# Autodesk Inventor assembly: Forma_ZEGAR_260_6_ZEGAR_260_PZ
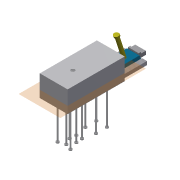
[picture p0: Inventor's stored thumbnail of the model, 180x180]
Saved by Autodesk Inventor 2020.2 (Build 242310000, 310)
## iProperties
Created: 2015-01
Part Number: Forma_ZEGAR_260_6_ZEGAR_260_PZ
Document SubType Name: Assembly
Designer: F.Stasiak
Catalog Web Link: www.expertbooks.pl
Manager: www.cadconsulting.pl
Company: Fabian Stasiak CAD Consulting
Author: F.Stasiak
Subject: Zbiór ćwiczeń. Autodesk Inventor 2020. Kurs Professional
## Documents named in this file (21)
- C:\2020_Kurs_Professional\R6 Formy\Komponenty\Forma_ZEGAR_260_6_ZEGAR_260_PZ.iam
- C:\2020_Kurs_Professional\R6 Formy\Komponenty\Forma_ZEGAR_260_6_ZEGAR_260_MP.ipt
- C:\2020_Kurs_Professional\R6 Formy\Komponenty\Forma_ZEGAR_260_6_ZEGAR_260_WP.ipt
- C:\2020_Kurs_Professional\R6 Formy\Komponenty\Forma_ZEGAR_260_6_ZEGAR_260_CR_Base.ipt
- C:\2020_Kurs_Professional\R6 Formy\Komponenty\Forma_ZEGAR_260_6_ZEGAR_260_CV_Base.ipt
- C:\2020_Kurs_Professional\R6 Formy\Komponenty\Rdzenie formujące\PUNCH_CDH\Forma_ZEGAR_260_5_ZEGAR_260_Rdzeń formujący2_Base.ipt
- C:\2020_Kurs_Professional\R6 Formy\Komponenty\Rdzenie formujące\PUNCH_CDH\Forma_ZEGAR_260_5_ZEGAR_260_Rdzeń formujący2_1.ipt
- C:\2020_Kurs_Professional\R6 Formy\Komponenty\Forma_ZEGAR_260_6_ZEGAR_260_IN1_Base.ipt
- C:\2020_Kurs_Professional\R6 Formy\Komponenty\Forma_ZEGAR_260_6_ZEGAR_260_IN1_1_1.ipt
- C:\2020_Kurs_Professional\R6 Formy\Komponenty\Wypychacze\DME_AH\Grupa EP1.0\Forma_ZEGAR_260_4_ZEGAR_260_Grupa EP1_EP1.ipt
- C:\2020_Kurs_Professional\R6 Formy\Komponenty\Wypychacze\DME_AH\Grupa EP1.0\Forma_ZEGAR_260_4_ZEGAR_260_Grupa EP1_EP2.ipt
- C:\2020_Kurs_Professional\R6 Formy\Komponenty\Wypychacze\DME_AH\Grupa EP1.0\Forma_ZEGAR_260_4_ZEGAR_260_Grupa EP1_EP3.ipt
- C:\2020_Kurs_Professional\R6 Formy\Komponenty\Wypychacze\DME_AH\Grupa EP1.0\Forma_ZEGAR_260_4_ZEGAR_260_Grupa EP1_EP4.ipt
- C:\2020_Kurs_Professional\R6 Formy\Komponenty\Wypychacze\DME_AH\Grupa EP1.0\Forma_ZEGAR_260_4_ZEGAR_260_Grupa EP1_EP5.ipt
- C:\2020_Kurs_Professional\R6 Formy\Komponenty\Wypychacze\DME_AH\Grupa EP1.0\Forma_ZEGAR_260_4_ZEGAR_260_Grupa EP1_EP6.ipt
- C:\2020_Kurs_Professional\R6 Formy\Komponenty\Wypychacze\DME_AH\Grupa EP1.0\Forma_ZEGAR_260_4_ZEGAR_260_Grupa EP1_EP7.ipt
- C:\2020_Kurs_Professional\R6 Formy\Komponenty\Wypychacze\DME_AH\Grupa EP1.0\Forma_ZEGAR_260_4_ZEGAR_260_Grupa EP1_EP8.ipt
- C:\2020_Kurs_Professional\R6 Formy\Komponenty\Wypychacze\DME_AH\Grupa EP1.0\Forma_ZEGAR_260_4_ZEGAR_260_Grupa EP1_EP9.ipt
- C:\2020_Kurs_Professional\R6 Formy\Komponenty\Wypychacze\DME_AH\Grupa EP1.0\Forma_ZEGAR_260_4_ZEGAR_260_Grupa EP1_EP10.ipt
- C:\2020_Kurs_Professional\R6 Formy\Komponenty\Wypychacze\DME_AH\Grupa EP1.0\Forma_ZEGAR_260_4_ZEGAR_260_Grupa EP1_EP11.ipt
- C:\2020_Kurs_Professional\R6 Formy\Komponenty\Suwaki\GENERIC_Zwykła blokada pojedyncza 1 1\Forma_ZEGAR_260_4_ZEGAR_260_SA1.iam
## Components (20 placed, 20 different names)
1. Forma_ZEGAR_260_4_ZEGAR_260_MP:1 — Równoległy:1, Równoległy:2, Równoległy:3, Równoległy:4, Równoległy:5, Równoległy:6, Równoległy:41
2. Forma_ZEGAR_260_4_ZEGAR_260_WP:1 — Równoległy:4, Równoległy:5, Równoległy:6
3. Forma_ZEGAR_260_4_ZEGAR_260_CR_Base:1 — Równoległy:7, Równoległy:8, Równoległy:9
4. Forma_ZEGAR_260_4_ZEGAR_260_CV_Base:1 — Równoległy:10, Równoległy:11, Równoległy:12
5. Forma_ZEGAR_260_4_ZEGAR_260_Rdzeń formujący2_Base:1 — Kąt:1, Równoległy:20, Równoległy:21, Równoległy:22, Równoległy:23
6. Forma_ZEGAR_260_4_ZEGAR_260_Rdzeń formujący2_1:1 — Równoległy:20, Równoległy:21, Równoległy:22
7. Forma_ZEGAR_260_4_ZEGAR_260_IN1_Base:1 — Równoległy:24, Równoległy:25, Równoległy:26, Równoległy:27, Równoległy:28, Równoległy:29
8. Forma_ZEGAR_260_4_ZEGAR_260_IN1_1_1:1 — Równoległy:27, Równoległy:28, Równoległy:29, Zestawiający:13
9. Forma_ZEGAR_260_4_ZEGAR_260_Grupa EP1_EP1:1 — Zestawiający:2, Równoległy:30, Kąt:2, Równoległy:41
10. Forma_ZEGAR_260_4_ZEGAR_260_Grupa EP1_EP2:1 — Zestawiający:3, Równoległy:31, Kąt:3
11. Forma_ZEGAR_260_4_ZEGAR_260_Grupa EP1_EP3:1 — Zestawiający:4, Równoległy:32, Kąt:4
12. Forma_ZEGAR_260_4_ZEGAR_260_Grupa EP1_EP4:1 — Zestawiający:5, Równoległy:33, Kąt:5
13. Forma_ZEGAR_260_4_ZEGAR_260_Grupa EP1_EP5:1 — Zestawiający:6, Równoległy:34, Kąt:6
14. Forma_ZEGAR_260_4_ZEGAR_260_Grupa EP1_EP6:1 — Zestawiający:7, Równoległy:35, Kąt:7
15. Forma_ZEGAR_260_4_ZEGAR_260_Grupa EP1_EP7:1 — Zestawiający:8, Równoległy:36, Kąt:8
16. Forma_ZEGAR_260_4_ZEGAR_260_Grupa EP1_EP8:1 — Zestawiający:9, Równoległy:37, Kąt:9
17. Forma_ZEGAR_260_4_ZEGAR_260_Grupa EP1_EP9:1 — Zestawiający:10, Równoległy:38, Kąt:10
18. Forma_ZEGAR_260_4_ZEGAR_260_Grupa EP1_EP10:1 — Zestawiający:11, Równoległy:39, Kąt:11
19. Forma_ZEGAR_260_4_ZEGAR_260_Grupa EP1_EP11:1 — Zestawiający:12, Równoległy:40, Kąt:12
20. Forma_ZEGAR_260_4_ZEGAR_260_SA1:1 [sub-assembly] — Zestawiający:13
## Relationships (58: Flush 34, Angle 12, Mate 12)
- Równoległy:1 [Flush]: Forma_ZEGAR_260_4_ZEGAR_260_MP:1
- Równoległy:2 [Flush]: Forma_ZEGAR_260_4_ZEGAR_260_MP:1
- Równoległy:3 [Flush]: Forma_ZEGAR_260_4_ZEGAR_260_MP:1
- Równoległy:4 [Flush]: Forma_ZEGAR_260_4_ZEGAR_260_MP:1 ↔ Forma_ZEGAR_260_4_ZEGAR_260_WP:1
- Równoległy:5 [Flush]: Forma_ZEGAR_260_4_ZEGAR_260_MP:1 ↔ Forma_ZEGAR_260_4_ZEGAR_260_WP:1
- Równoległy:6 [Flush]: Forma_ZEGAR_260_4_ZEGAR_260_MP:1 ↔ Forma_ZEGAR_260_4_ZEGAR_260_WP:1
- Równoległy:7 [Flush]: Forma_ZEGAR_260_4_ZEGAR_260_CR_Base:1
- Równoległy:8 [Flush]: Forma_ZEGAR_260_4_ZEGAR_260_CR_Base:1
- Równoległy:9 [Flush]: Forma_ZEGAR_260_4_ZEGAR_260_CR_Base:1
- Równoległy:10 [Flush]: Forma_ZEGAR_260_4_ZEGAR_260_CV_Base:1
- Równoległy:11 [Flush]: Forma_ZEGAR_260_4_ZEGAR_260_CV_Base:1
- Równoległy:12 [Flush]: Forma_ZEGAR_260_4_ZEGAR_260_CV_Base:1
- Kąt:1 [Angle]: Forma_ZEGAR_260_4_ZEGAR_260_Rdzeń formujący2_Base:1
- Równoległy:20 [Flush]: Forma_ZEGAR_260_4_ZEGAR_260_Rdzeń formujący2_Base:1 ↔ Forma_ZEGAR_260_4_ZEGAR_260_Rdzeń formujący2_1:1
- Równoległy:21 [Flush]: Forma_ZEGAR_260_4_ZEGAR_260_Rdzeń formujący2_Base:1 ↔ Forma_ZEGAR_260_4_ZEGAR_260_Rdzeń formujący2_1:1
- Równoległy:22 [Flush]: Forma_ZEGAR_260_4_ZEGAR_260_Rdzeń formujący2_Base:1 ↔ Forma_ZEGAR_260_4_ZEGAR_260_Rdzeń formujący2_1:1
- Równoległy:23 [Flush]: Forma_ZEGAR_260_4_ZEGAR_260_Rdzeń formujący2_Base:1
- Równoległy:24 [Flush]: Forma_ZEGAR_260_4_ZEGAR_260_IN1_Base:1
- Równoległy:25 [Flush]: Forma_ZEGAR_260_4_ZEGAR_260_IN1_Base:1
- Równoległy:26 [Flush]: Forma_ZEGAR_260_4_ZEGAR_260_IN1_Base:1
- Równoległy:27 [Flush]: Forma_ZEGAR_260_4_ZEGAR_260_IN1_Base:1 ↔ Forma_ZEGAR_260_4_ZEGAR_260_IN1_1_1:1
- Równoległy:28 [Flush]: Forma_ZEGAR_260_4_ZEGAR_260_IN1_Base:1 ↔ Forma_ZEGAR_260_4_ZEGAR_260_IN1_1_1:1
- Równoległy:29 [Flush]: Forma_ZEGAR_260_4_ZEGAR_260_IN1_Base:1 ↔ Forma_ZEGAR_260_4_ZEGAR_260_IN1_1_1:1
- Zestawiający:2 [Mate]: Forma_ZEGAR_260_4_ZEGAR_260_Grupa EP1_EP1:1
- Równoległy:30 [Flush]: Forma_ZEGAR_260_4_ZEGAR_260_Grupa EP1_EP1:1
- Kąt:2 [Angle]: Forma_ZEGAR_260_4_ZEGAR_260_Grupa EP1_EP1:1
- Zestawiający:3 [Mate]: Forma_ZEGAR_260_4_ZEGAR_260_Grupa EP1_EP2:1
- Równoległy:31 [Flush]: Forma_ZEGAR_260_4_ZEGAR_260_Grupa EP1_EP2:1
- Kąt:3 [Angle]: Forma_ZEGAR_260_4_ZEGAR_260_Grupa EP1_EP2:1
- Zestawiający:4 [Mate]: Forma_ZEGAR_260_4_ZEGAR_260_Grupa EP1_EP3:1
- Równoległy:32 [Flush]: Forma_ZEGAR_260_4_ZEGAR_260_Grupa EP1_EP3:1
- Kąt:4 [Angle]: Forma_ZEGAR_260_4_ZEGAR_260_Grupa EP1_EP3:1
- Zestawiający:5 [Mate]: Forma_ZEGAR_260_4_ZEGAR_260_Grupa EP1_EP4:1
- Równoległy:33 [Flush]: Forma_ZEGAR_260_4_ZEGAR_260_Grupa EP1_EP4:1
- Kąt:5 [Angle]: Forma_ZEGAR_260_4_ZEGAR_260_Grupa EP1_EP4:1
- Zestawiający:6 [Mate]: Forma_ZEGAR_260_4_ZEGAR_260_Grupa EP1_EP5:1
- Równoległy:34 [Flush]: Forma_ZEGAR_260_4_ZEGAR_260_Grupa EP1_EP5:1
- Kąt:6 [Angle]: Forma_ZEGAR_260_4_ZEGAR_260_Grupa EP1_EP5:1
- Zestawiający:7 [Mate]: Forma_ZEGAR_260_4_ZEGAR_260_Grupa EP1_EP6:1
- Równoległy:35 [Flush]: Forma_ZEGAR_260_4_ZEGAR_260_Grupa EP1_EP6:1
- Kąt:7 [Angle]: Forma_ZEGAR_260_4_ZEGAR_260_Grupa EP1_EP6:1
- Zestawiający:8 [Mate]: Forma_ZEGAR_260_4_ZEGAR_260_Grupa EP1_EP7:1
- Równoległy:36 [Flush]: Forma_ZEGAR_260_4_ZEGAR_260_Grupa EP1_EP7:1
- Kąt:8 [Angle]: Forma_ZEGAR_260_4_ZEGAR_260_Grupa EP1_EP7:1
- Zestawiający:9 [Mate]: Forma_ZEGAR_260_4_ZEGAR_260_Grupa EP1_EP8:1
- Równoległy:37 [Flush]: Forma_ZEGAR_260_4_ZEGAR_260_Grupa EP1_EP8:1
- Kąt:9 [Angle]: Forma_ZEGAR_260_4_ZEGAR_260_Grupa EP1_EP8:1
- Zestawiający:10 [Mate]: Forma_ZEGAR_260_4_ZEGAR_260_Grupa EP1_EP9:1
- Równoległy:38 [Flush]: Forma_ZEGAR_260_4_ZEGAR_260_Grupa EP1_EP9:1
- Kąt:10 [Angle]: Forma_ZEGAR_260_4_ZEGAR_260_Grupa EP1_EP9:1
- Zestawiający:11 [Mate]: Forma_ZEGAR_260_4_ZEGAR_260_Grupa EP1_EP10:1
- Równoległy:39 [Flush]: Forma_ZEGAR_260_4_ZEGAR_260_Grupa EP1_EP10:1
- Kąt:11 [Angle]: Forma_ZEGAR_260_4_ZEGAR_260_Grupa EP1_EP10:1
- Zestawiający:12 [Mate]: Forma_ZEGAR_260_4_ZEGAR_260_Grupa EP1_EP11:1
- Równoległy:40 [Flush]: Forma_ZEGAR_260_4_ZEGAR_260_Grupa EP1_EP11:1
- Kąt:12 [Angle]: Forma_ZEGAR_260_4_ZEGAR_260_Grupa EP1_EP11:1
- Zestawiający:13 [Mate]: Forma_ZEGAR_260_4_ZEGAR_260_IN1_1_1:1 ↔ Forma_ZEGAR_260_4_ZEGAR_260_SA1:1
- Równoległy:41 [Flush]: Forma_ZEGAR_260_4_ZEGAR_260_MP:1 ↔ Forma_ZEGAR_260_4_ZEGAR_260_Grupa EP1_EP1:1
